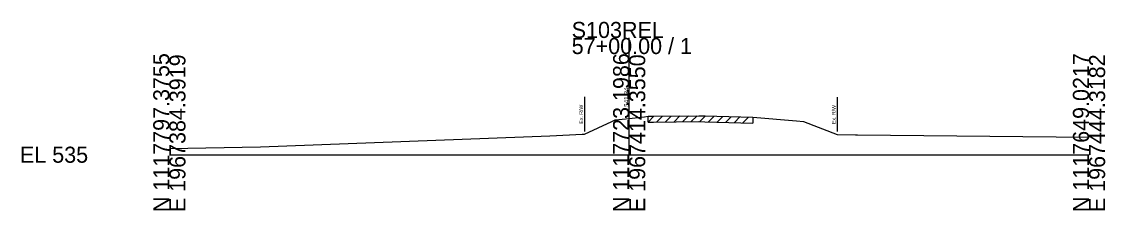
# Model space of a CAD drawing. Extents: x -26 to 163, y -10 to 24518.
# Drawn here: x -25.7 to 162.8, y 7490.3 to 7523.2 of the extents above; entities that cross this region are included whole.
import ezdxf

# ---------------------------------------------------------------- set-up
doc = ezdxf.new("R2010")
doc.units = 0
for name, color, linetype in [('RD_GPK_XS_Cell', 7, 'Continuous'), ('RD_XS_ExGround', 7, 'Continuous'), ('RD_XS_ExPaveRet', 7, 'Continuous'), ('RD_XS_ExRW', 7, 'Continuous'), ('RD_XS_TX_Elev_EX', 7, 'Continuous')]:
    doc.layers.add(name, color=color, linetype=linetype)

msp = doc.modelspace()

# ---------------------------------------------------------------- linework, layer by layer
at = {"layer": 'RD_GPK_XS_Cell'}
for p, q in [((80, 7500), (80, 7520.34)), ((0, 7500), (80, 7500)), ((80, 7500), (160, 7500))]:
    msp.add_line(p, q, dxfattribs=at)
at = {"layer": 'RD_XS_ExGround'}
msp.add_lwpolyline([(0, 7501.06), (15.87, 7501.38), (66.21, 7503.3), (69.64, 7503.45), (71.84, 7503.57), (72.21, 7503.57), (76.98, 7505.81), (77.57, 7506.08), (80, 7506.34), (82.67, 7506.62), (83.3, 7506.69), (84.22, 7506.7), (92.11, 7506.78), (93.18, 7506.75), (101.54, 7506.52), (109.12, 7505.89), (110.33, 7505.78), (116.18, 7503.52), (119.35, 7503.44), (119.7, 7503.45), (160, 7503.05)], dxfattribs=at)
at = {"layer": 'RD_XS_ExPaveRet'}
for p, q in [((83.3, 7505.69), (84.31, 7506.7)), ((83.3, 7505.69), (83.3, 7506.69)), ((83.3, 7505.69), (84.22, 7505.7)), ((84.22, 7505.7), (92.11, 7505.78)), ((84.8, 7505.71), (85.81, 7506.72)), ((86.3, 7505.72), (87.31, 7506.73)), ((87.8, 7505.74), (88.81, 7506.75)), ((89.3, 7505.75), (90.31, 7506.76)), ((90.8, 7505.77), (91.81, 7506.78)), ((92.11, 7505.78), (93.18, 7505.75)), ((92.3, 7505.78), (93.27, 7506.75)), ((93.18, 7505.75), (101.54, 7505.52)), ((93.8, 7505.74), (94.77, 7506.71)), ((95.3, 7505.7), (96.27, 7506.67)), ((96.8, 7505.65), (97.77, 7506.63)), ((98.3, 7505.61), (99.27, 7506.59)), ((99.8, 7505.57), (100.77, 7506.55)), ((101.54, 7506.52), (101.54, 7505.52))]:
    msp.add_line(p, q, dxfattribs=at)
at = {"layer": 'RD_XS_ExRW'}
for p, q in [((72.21, 7510.07), (72.21, 7504.07)), ((116.18, 7510.02), (116.18, 7504.02))]:
    msp.add_line(p, q, dxfattribs=at)

# ---------------------------------------------------------------- texts
at = {"layer": 'RD_GPK_XS_Cell'}
for s, p in [('S103REL', (70, 7520.34)), ('57+00.00 / 1', (70, 7517.54)), ('EL 535', (-26, 7498.6))]:
    msp.add_text(s, height=2.8, dxfattribs=at).set_placement(p)
for s, p in [('N 1117797.3755', (0, 7490)), ('E 1967384.3919', (2.8, 7490)), ('N 1117723.1986', (80, 7490)), ('E 1967414.3550', (82.8, 7490)), ('N 1117649.0217', (160, 7490)), ('E 1967444.3182', (162.8, 7490))]:
    msp.add_text(s, height=2.8, rotation=90, dxfattribs=at).set_placement(p)
at = {"layer": 'RD_XS_ExRW'}
for p in [(71.96, 7505.42), (115.93, 7505.36)]:
    msp.add_text('Ex. R/W ', height=0.65, rotation=90, dxfattribs=at).set_placement(p)
at = {"layer": 'RD_XS_TX_Elev_EX'}
msp.add_text('541.34', height=0.8, rotation=90, dxfattribs=at).set_placement((79.9, 7508.34))

doc.saveas('drawing.dxf')
